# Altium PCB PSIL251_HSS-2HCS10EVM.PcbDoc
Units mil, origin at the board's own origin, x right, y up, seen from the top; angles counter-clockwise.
Board outline 1250 x 1801.18 mil, 4 copper layers (Top Layer, Layer 1, Layer 2, Bottom Layer), stack 49.606 mil thick; 8 components, 13 nets, 43 pads, 12 vias.
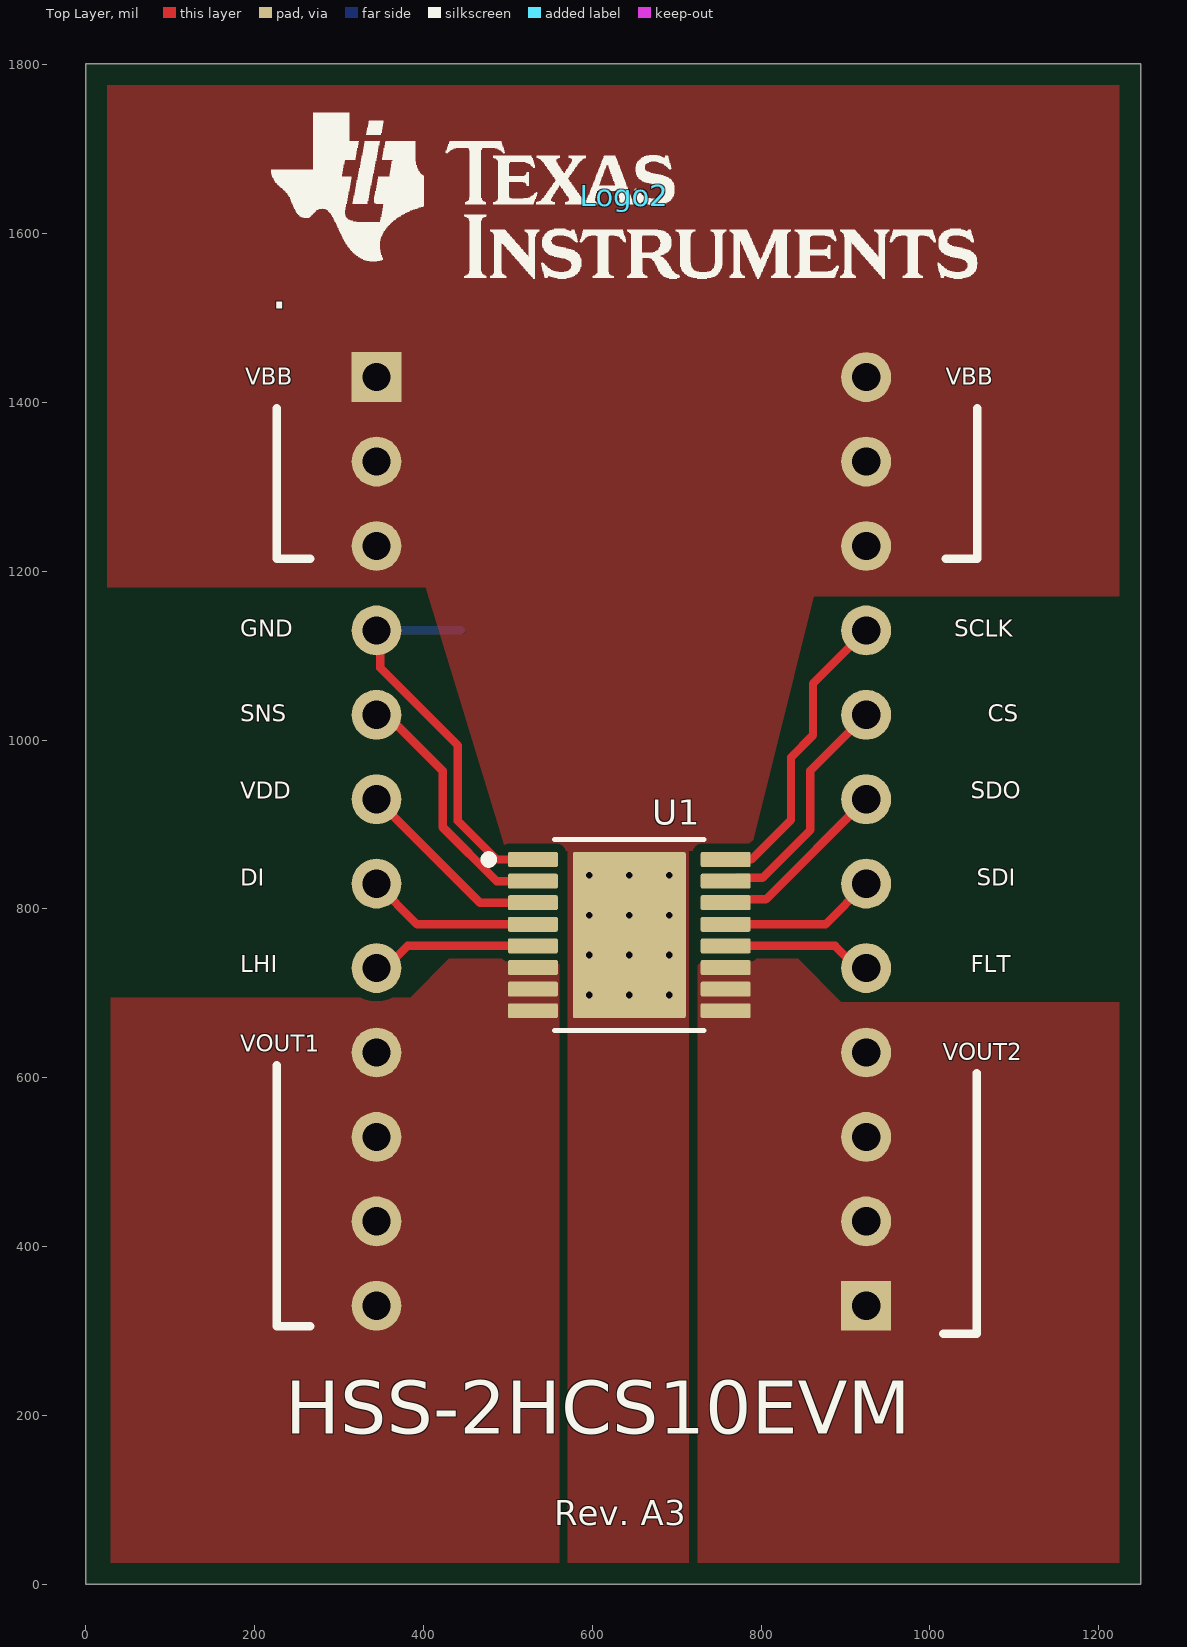
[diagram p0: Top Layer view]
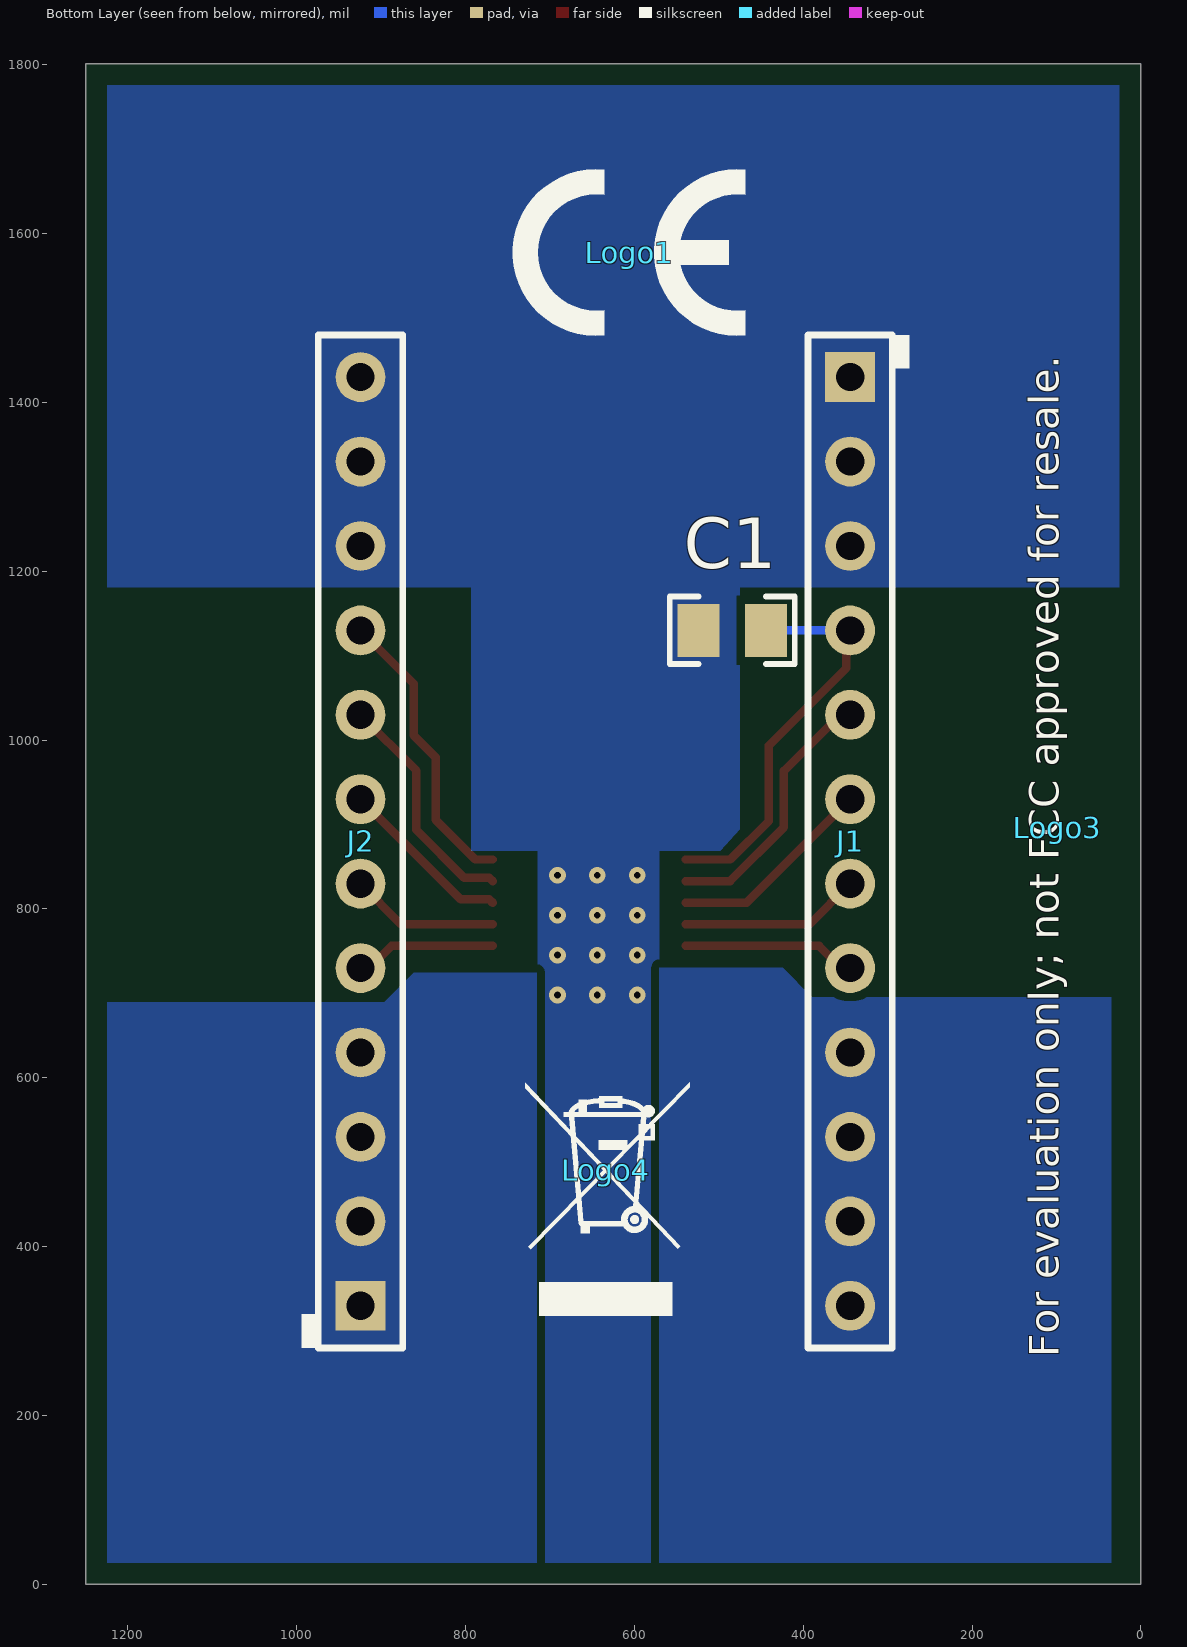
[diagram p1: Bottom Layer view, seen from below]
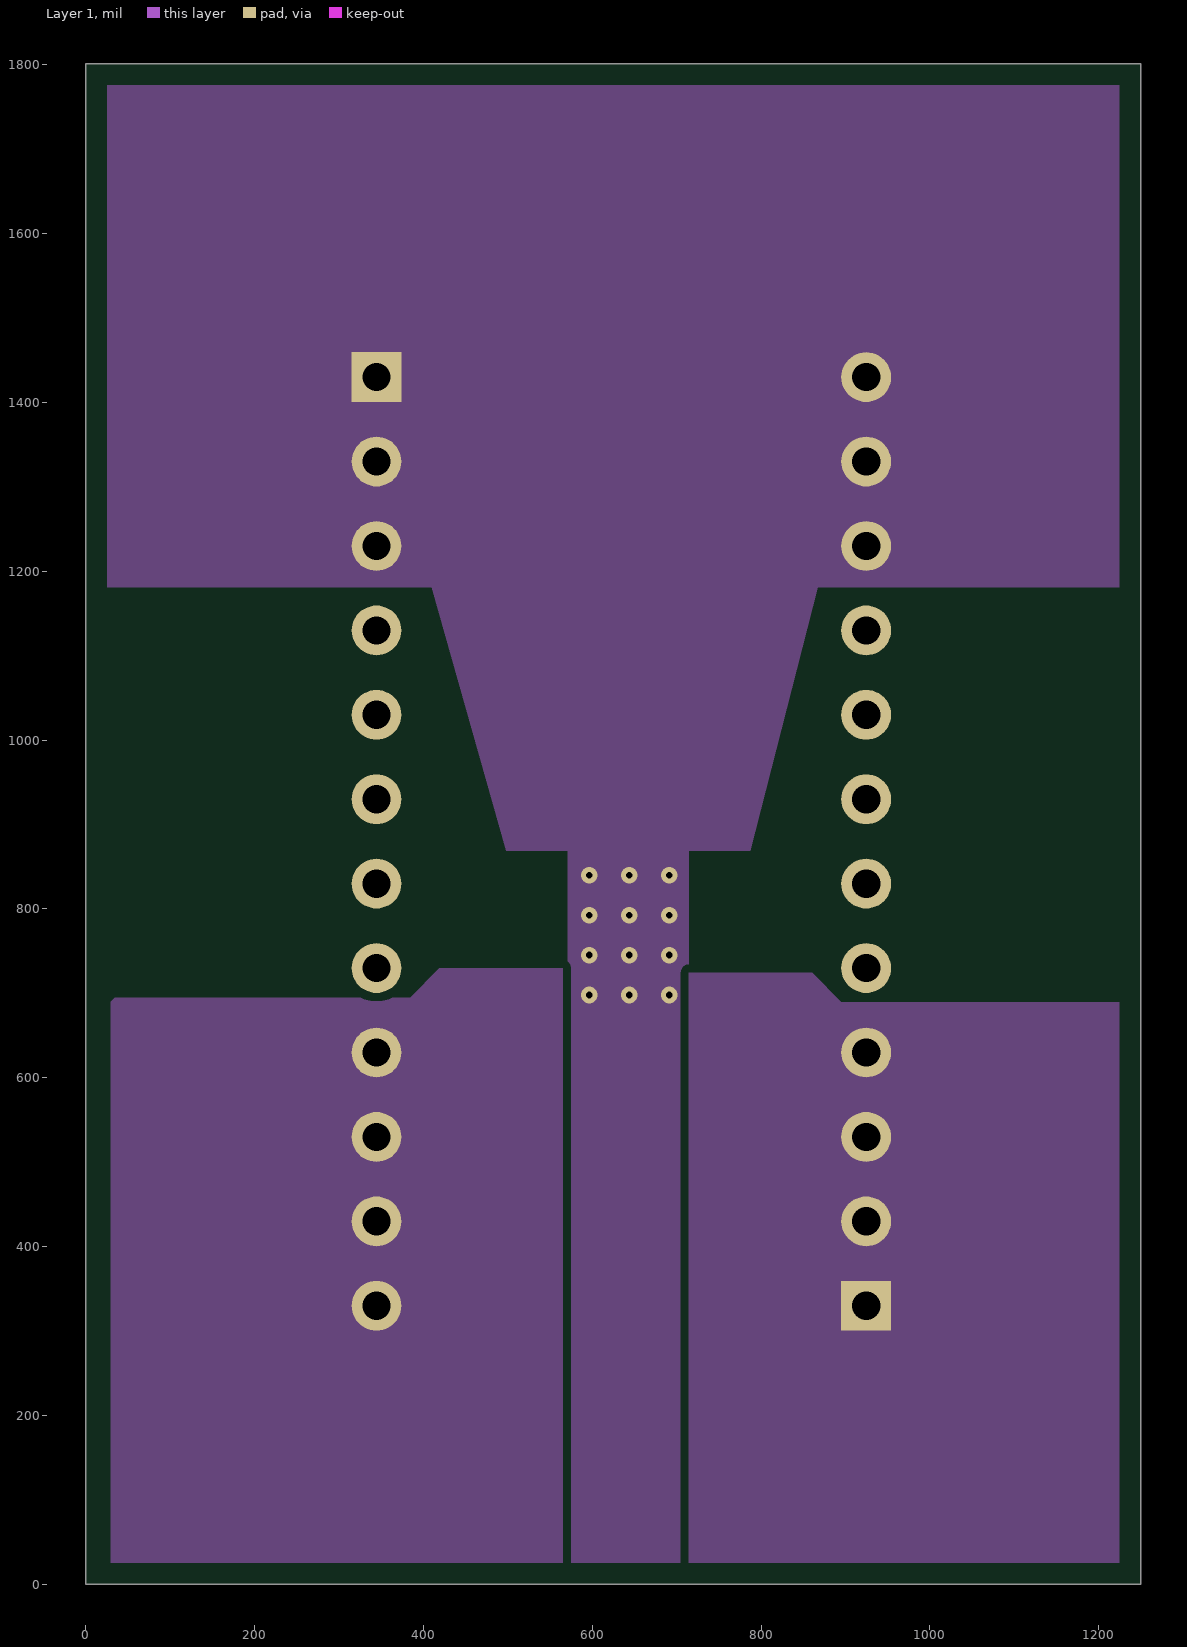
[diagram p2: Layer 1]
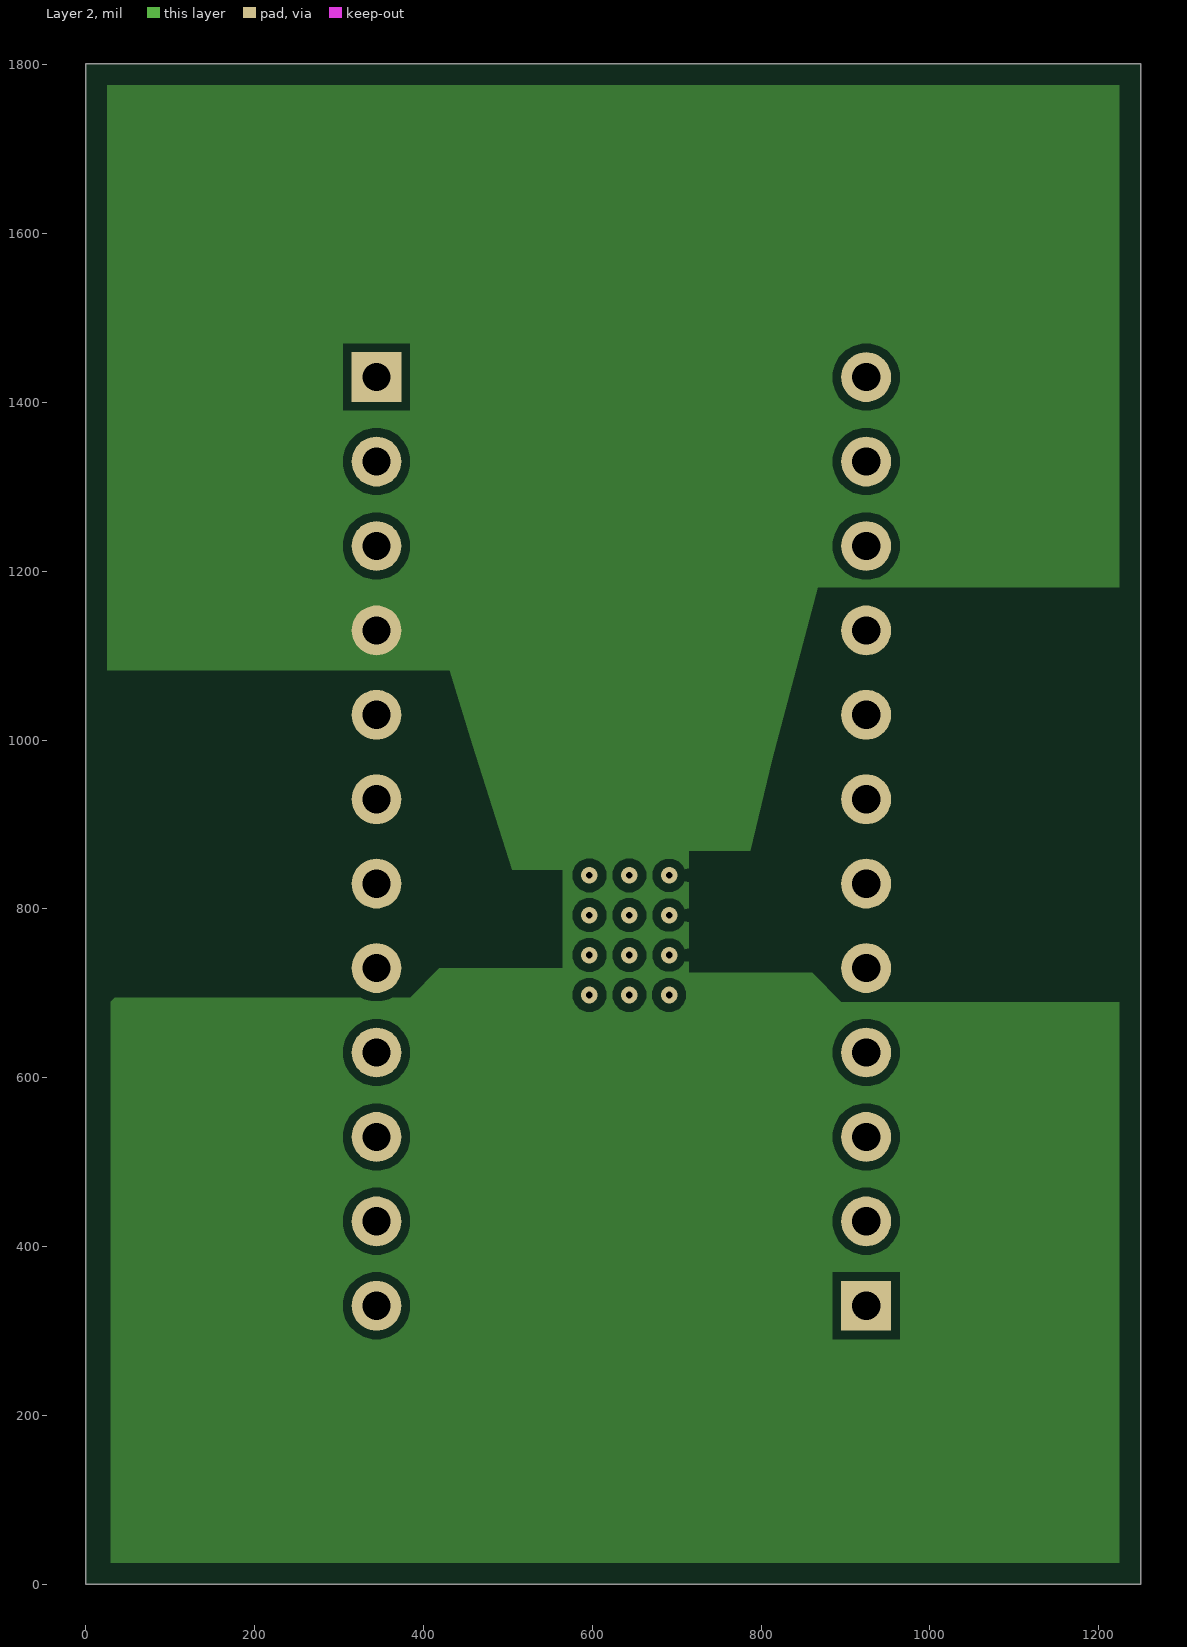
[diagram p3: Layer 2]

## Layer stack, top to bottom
Top Solder: solder mask 0.4, Solder Resist, Dk 3.5
Top Layer: signal copper 1.4
Dielectric 1: prepreg 1.7016, PP-006, Dk 4.1
Layer 1: signal copper 1.7016
Dielectric1: core 40, FR-4 High Tg, Dk 4.8
Layer 2: signal copper 1.7016
Dielectric 2: prepreg 1.7016, PP-006, Dk 4.1
Bottom Layer: signal copper 1.4
Bottom Solder: solder mask 0.4, Solder Resist, Dk 3.5

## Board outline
0,0 1250,0 1250,1801.18 0,1801.18

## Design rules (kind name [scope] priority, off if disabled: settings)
AcuteAngle [All] p1: minimum=4.50000000000000E+0001 checktracksonly=FALSE
AssemblyTestPointUsage [All] p1: valid=2
BoardOutlineClearance BoardOutlineClearance_MountingHoles [OnCopper and InComponentClass('Mounting Holes')] p1: gap=39.37 ignorepadtopadclearanceinfootprint=FALSE
BoardOutlineClearance BoardOutlineClearance_Poly [OnCopper and IsPoly] p2: gap=25 ignorepadtopadclearanceinfootprint=FALSE
BoardOutlineClearance [OnCopper and Not InComponentClass('Logo') and not InComponentClass('FiducialMark') and not InRegion(1000,500,4000,800) and not InPoly] p3: gap=40 ignorepadtopadclearanceinfootprint=FALSE
Clearance Clearance_Keepouts [((IsTrack Or IsArc) And Not InPoly) And IsFree and IsKeepOut vs ((IsTrack Or IsArc) And Not InPoly) And IsFree and IsKeepOut] p1: gap=0 ignorepadtopadclearanceinfootprint=FALSE
Clearance Clearance_Poly [InPolygon] p2: gap=10 ignorepadtopadclearanceinfootprint=TRUE
Clearance Clearance_FiducialMark [IsKeepOut and InComponentClass('FiducialMark') vs IsPad and InComponentClass('FiducialMark')] p3: gap=0 ignorepadtopadclearanceinfootprint=FALSE
Clearance [All] p4: gap=7.87 ignorepadtopadclearanceinfootprint=TRUE
ComponentClearance ComponentClearance_MountingHoles_FiducialMarks [InComponentClass('Mounting Holes') vs InComponentClass('FiducialMark')] p1: gap=50 collisioncheckmode=3 verticalgap=10 showdistances=FALSE
ComponentClearance ComponentClearance_Shunt [InComponentClass('Header') vs InComponentClass('Shunt')] p2: gap=0 collisioncheckmode=3 verticalgap=0 showdistances=FALSE
ComponentClearance ComponentClearance_Logo [InComponentClass('Logo')] p3: gap=30 collisioncheckmode=3 verticalgap=10 showdistances=FALSE
ComponentClearance ComponentClearance_ScrewToNut [(HasFootprint('NY PMS 440 0025 PH')) vs (HasFootprint('Keystone_1902C'))] p4: gap=5 collisioncheckmode=3 verticalgap=10 showdistances=FALSE
ComponentClearance ComponentClearance_MountingHoles [InComponentClass('Mounting Holes')] p5: gap=100 collisioncheckmode=3 verticalgap=100000 showdistances=FALSE
ComponentClearance ComponentClearance_SmallPassives [HasFootprint('0201*') or HasFootprint('0402*') or HasFootprint('0508') or HasFootprint('0603*') or HasFootprint('0612') or HasFootprint('0805*') or HasFootprint('0815*') or HasFootprint('0830*') or HasFootprint('1206*') or HasFootprint('1210*') or HasFootprint('1808*') or HasFootprint('1812*') or HasFootprint('1825*') or HasFootprint('2010*') or HasFootprint('2220*') or HasFootprint('2225*') or HasFootprint('2512*') or HasFootprint('2728*') or HasFootprint('3518*') vs HasFootprint('0201*') or HasFootprint('0402*') or HasFootprint('0508') or HasFootprint('0603*') or HasFootprint('0612') or HasFootprint('0805*') or HasFootprint('0815*') or HasFootprint('0830*') or HasFootprint('1206*') or HasFootprint('1210*') or HasFootprint('1808*') or HasFootprint('1812*') or HasFootprint('1825*') or HasFootprint('2010*') or HasFootprint('2220*') or HasFootprint('2225*') or HasFootprint('2512*') or HasFootprint('2728*') or HasFootprint('3518*')] p6: gap=14.96 collisioncheckmode=3 verticalgap=10 showdistances=FALSE
ComponentClearance ComponentClearance_THtoSMT [IsThruComponent vs IsSMTComponent] p7: gap=30 collisioncheckmode=3 verticalgap=30 showdistances=FALSE
ComponentClearance ComponentClearance_THtoTH [IsThruComponent vs IsThruComponent] p8: gap=20 collisioncheckmode=3 verticalgap=30 showdistances=FALSE
ComponentClearance [All] p9: gap=20 collisioncheckmode=3 verticalgap=10 showdistances=FALSE
DiffPairsRouting [All] p1: maxlimit=100 minlimit=10 mostfreqgap=10 toplayer_minwidth=15 toplayer_maxwidth=15 toplayer_prefwidth=15 midlayer1_minwidth=15 midlayer1_maxwidth=15 midlayer1_prefwidth=15 midlayer2_minwidth=15 midlayer2_maxwidth=15 midlayer2_prefwidth=15 bottomlayer_minwidth=15 bottomlayer_maxwidth=15 bottomlayer_prefwidth=15 maxuncoupledlength=1000
FabricationTestPointUsage TestPointUsage [All] p1: valid=2 allowmultiple=FALSE
FabricationTestpoint Testpoint [All] p1: side=3 testpointundercomponent=TRUE minsize=40 maxsize=100 preferedsize=60 minholesize=0 maxholesize=40 preferedholesize=32 testpointgrid=1 allowsidetop=TRUE allowsidebottom=TRUE usegrid=TRUE gridtolerance=0.01
FanoutControl Fanout_LCC [IsLCC] p1: bgadir=Out bgaviamode=Centered fanoutstyle=Auto fanoutdirection=Alternating viagrid=1 // Fanout_LCC (Default Rule)
FanoutControl Fanout_BGA [IsBGA] p2: bgadir=Out bgaviamode=Centered fanoutstyle=Auto fanoutdirection=Alternating viagrid=1 // Fanout_BGA (Default Rule)
FanoutControl Fanout_Default [All] p4: bgadir=Out bgaviamode=Centered fanoutstyle=Auto fanoutdirection=Alternating viagrid=1 // Fanout_Default (Default Rule)
FanoutControl Fanout_Small [(CompPinCount < 5)] p5: bgadir=Out bgaviamode=Centered fanoutstyle=Auto fanoutdirection=OutThenIn viagrid=1 // Fanout_Small (Default Rule)
HoleSize [All] p1: absolutevalues=TRUE maxlimit=251 minlimit=7.87 maxpercent=80.000 minpercent=20.000
MinimumAnnularRing MinimumAnnularRing_ThermalPadVias [IsVia and InAnyComponent] p1: minimumring=5.91
MinimumAnnularRing [All] p2: minimumring=7.87
MinimumSolderMaskSliver MinimumSolderMaskSliver_Logo [InComponentClass('Logo') vs InComponentClass('Logo')] p1: minsoldermaskwidth=0.7
MinimumSolderMaskSliver [All] p2: minsoldermaskwidth=3.94
PlaneConnect [All] p1: planeconnectstyle=Relief reliefexpansion=10 reliefentries=4 reliefconductorwidth=10 reliefairgap=10
PolygonConnect PolygonConnect_8 [All vs IsNamedPolygon('Top Layer-VBB_1') Or IsNamedPolygon('TOP_LAYER_VOUT1_P008') Or IsNamedPolygon('TOP_LAYER_VOUT2_P006') Or IsNamedPolygon('Layer 1-VBB_1') Or IsNamedPolygon('LAYER_1_VOUT1_P007') Or IsNamedPolygon('LAYER_1_VOUT2_P009') Or IsNamedPolygon('LAYER_2_GND_P017') Or IsNamedPolygon('Bottom Layer-VBB_1') Or IsNamedPolygon('BOTTOM_LAYER_VOUT1_P011') Or IsNamedPolygon('BOTTOM_LAYER_VOUT2_P010')] p1: connectstyle=Direct reliefconductorwidth=10 reliefentries=4 polygonreliefangle="90 Angle" airgapwidth=10
PolygonConnect PolygonConnect_7 [All vs IsNamedPolygon('LAYER_1_VOUT2_P009')] p2: thpad.connectstyle=Direct thpad.reliefconductorwidth=10 thpad.reliefentries=4 thpad.polygonreliefangle="90 Angle" thpad.airgapwidth=10 smdpad.connectstyle=Direct smdpad.reliefconductorwidth=10 smdpad.reliefentries=4 smdpad.polygonreliefangle="90 Angle" smdpad.airgapwidth=10 via.connectstyle=Relief via.reliefconductorwidth=10 via.reliefentries=4 via.polygonreliefangle="90 Angle" via.airgapwidth=10
PolygonConnect PolygonConnect_6 [All vs IsNamedPolygon('LAYER_2_GND_P014')] p3: thpad.connectstyle=Direct thpad.reliefconductorwidth=10 thpad.reliefentries=4 thpad.polygonreliefangle="90 Angle" thpad.airgapwidth=10 smdpad.connectstyle=Direct smdpad.reliefconductorwidth=10 smdpad.reliefentries=4 smdpad.polygonreliefangle="90 Angle" smdpad.airgapwidth=10 via.connectstyle=Relief via.reliefconductorwidth=10 via.reliefentries=4 via.polygonreliefangle="90 Angle" via.airgapwidth=10
PolygonConnect PolygonConnect_5 [All vs IsNamedPolygon('BOTTOM_LAYER_VOUT2_P010')] p4: thpad.connectstyle=Direct thpad.reliefconductorwidth=10 thpad.reliefentries=4 thpad.polygonreliefangle="90 Angle" thpad.airgapwidth=10 smdpad.connectstyle=Direct smdpad.reliefconductorwidth=10 smdpad.reliefentries=4 smdpad.polygonreliefangle="90 Angle" smdpad.airgapwidth=10 via.connectstyle=Relief via.reliefconductorwidth=10 via.reliefentries=4 via.polygonreliefangle="90 Angle" via.airgapwidth=10
PolygonConnect PolygonConnect_4 [All vs IsNamedPolygon('BOTTOM_LAYER_VOUT1_P011')] p5: thpad.connectstyle=Direct thpad.reliefconductorwidth=10 thpad.reliefentries=4 thpad.polygonreliefangle="90 Angle" thpad.airgapwidth=10 smdpad.connectstyle=Direct smdpad.reliefconductorwidth=10 smdpad.reliefentries=4 smdpad.polygonreliefangle="90 Angle" smdpad.airgapwidth=10 via.connectstyle=Relief via.reliefconductorwidth=10 via.reliefentries=4 via.polygonreliefangle="90 Angle" via.airgapwidth=10
PolygonConnect PolygonConnect_3 [All vs IsNamedPolygon('TOP_LAYER_VOUT2_P006')] p6: thpad.connectstyle=Direct thpad.reliefconductorwidth=10 thpad.reliefentries=4 thpad.polygonreliefangle="90 Angle" thpad.airgapwidth=10 smdpad.connectstyle=Direct smdpad.reliefconductorwidth=10 smdpad.reliefentries=4 smdpad.polygonreliefangle="90 Angle" smdpad.airgapwidth=10 via.connectstyle=Relief via.reliefconductorwidth=10 via.reliefentries=4 via.polygonreliefangle="90 Angle" via.airgapwidth=10
PolygonConnect PolygonConnect_2 [All vs IsNamedPolygon('TOP_LAYER_VOUT1_P008')] p7: thpad.connectstyle=Direct thpad.reliefconductorwidth=10 thpad.reliefentries=4 thpad.polygonreliefangle="90 Angle" thpad.airgapwidth=10 smdpad.connectstyle=Direct smdpad.reliefconductorwidth=10 smdpad.reliefentries=4 smdpad.polygonreliefangle="90 Angle" smdpad.airgapwidth=10 via.connectstyle=Relief via.reliefconductorwidth=10 via.reliefentries=4 via.polygonreliefangle="90 Angle" via.airgapwidth=10
PolygonConnect PolygonConnect_1 [All vs IsNamedPolygon('Top Layer-VBB_1') Or IsNamedPolygon('TOP_LAYER_VOUT1_1_P008') Or IsNamedPolygon('TOP_LAYER_VOUT2_1_P006') Or IsNamedPolygon('Layer 1-VBB_1') Or IsNamedPolygon('LAYER_1_VOUT1_P007') Or IsNamedPolygon('LAYER_1_VOUT2_1_P009') Or IsNamedPolygon('LAYER_2_GND_1_P014') Or IsNamedPolygon('Bottom Layer-VBB_1') Or IsNamedPolygon('BOTTOM_LAYER_VOUT1_1_P011') Or IsNamedPolygon('BOTTOM_LAYER_VOUT2_1_P010')] p8: connectstyle=Direct reliefconductorwidth=10 reliefentries=4 polygonreliefangle="90 Angle" airgapwidth=10
PolygonConnect [All] p9: connectstyle=Relief reliefconductorwidth=10 reliefentries=4 polygonreliefangle="90 Angle" airgapwidth=10
RoutingLayers [All] p1: top layer_v5=TRUE mid layer 1_v5=FALSE mid layer 2_v5=FALSE bottom layer_v5=TRUE
RoutingVias ThermalPadVias [IsVia and InAnyComponent] p1: holewidth=7.87 width=19.68 viastyle="Through Hole" minholewidth=7.87 minwidth=19.68 maxholewidth=12.99 maxwidth=23.62
RoutingVias [All] p2: holewidth=16 width=34 viastyle="Through Hole" minholewidth=7.87 minwidth=24 maxholewidth=40 maxwidth=65
SilkToBoardRegionClearance [Not ((IsComment or IsDesignator) And (Hide <> 'False')) and not InRegion(1000,500,4000,800)] p1:
SilkToSilkClearance SilkToSilkClearance_Pb-FreeLogo [(HasFootprint('Pb-Free_Overlay_Medium') OR HasFootprint('Pb-Free_Overlay_Small')) vs (HasFootprint('Pb-Free_Overlay_Medium') OR HasFootprint('Pb-Free_Overlay_Small'))] p1: silktosilkclearance=0
SilkToSilkClearance [All] p2: silktosilkclearance=3.94
SilkToSolderMaskClearance SilkToComponentPadClearance [(IsPad or IsFill or IsRegion) and InAnycomponent] p1: minsilkscreentomaskgap=5 clearancetoexposedcopper=TRUE
SilkToSolderMaskClearance "Silk to Solder Mask Opening" [All] p2: minsilkscreentomaskgap=3.94 clearancetoexposedcopper=FALSE
SolderMaskExpansion [All] p1: expansion=1.97 istentingtop=FALSE
UnRoutedNet [All] p1: checkbadconnections=TRUE
Width [All] p1: maxlimit=100 minlimit=6 preferedwidth=10 checkconnectedcopper=TRUE
13 further rules are at their usual default settings.

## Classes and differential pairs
component class Header: J1 J2
component class PSIL251_HSS-2HCS10EVM: C1 J1 J2 U1

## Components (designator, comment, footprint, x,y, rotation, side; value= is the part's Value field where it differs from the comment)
C1 "CGA4C2NP01H472J060AA" 0805_HV 484.13,1129.92 r180 bottom value=4700pF
J1 "800-10-012-10-001000" Mill-Max_800-10-012-10-001000 344.49,879.92 r270 bottom
J2 "800-10-012-10-001000" Mill-Max_800-10-012-10-001000 924.49,879.92 r90 bottom
Logo1 "CE Mark" CE_Mark_5mm 606.34,1577.52 r180 bottom
Logo2 "Texas Instruments" TI_Stacked_Overlay_Small 637.96,1644.76 r0 top
Logo3 "FCC disclaimer" FCC_disclaimer 99.47,895.88 r90 bottom
Logo4 "WEEE logo" WEEE_Minimum 633.84,490.39 r180 bottom
U1 "TPS2HC10SF-Q1" PWP0016M-MFG 643.87,768.97 r0 top

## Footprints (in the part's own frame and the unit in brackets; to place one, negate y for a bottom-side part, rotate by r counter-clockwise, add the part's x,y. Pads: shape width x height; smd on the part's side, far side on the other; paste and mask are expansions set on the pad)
0805_HV [mil] "0805 with 30mil clearance between pads"
  rect 50x63 smd: 1(-40,0) 2(40,0)
  silkscreen extent -74,-40 74,40, body extent -43,-29 43,29, height 57
CE_Mark_5mm [mil] "Minimum text height for CE Mark"
  silkscreen extent -138,-98 138,98
FCC_disclaimer [mil]
Mill-Max_800-10-012-10-001000 [mm] "Mill-Max"
  rect 1.5x1.5 hole 0.85: 1(-13.97,0)
  round 1.5 hole 0.85: 2(-11.43,0) 3(-8.89,0) 4(-6.35,0) 5(-3.81,0) 6(-1.27,0) 7(1.27,0) 8(3.81,0) 9(6.35,0) 10(8.89,0) 11(11.43,0) 12(13.97,0)
  silkscreen extent -15.24,-1.27 15.24,1.78, body extent -15.24,-1.27 15.24,1.27, height 8.13
PWP0016M-MFG [mm]
  rrect22% 1.5x0.45 smd paste+0 mask+0: 1(-2.9,2.275) 2(-2.9,1.625) 3(-2.9,0.975) 4(-2.9,0.325) 5(-2.9,-0.325) 6(-2.9,-0.975) 7(-2.9,-1.625) 8(-2.9,-2.275) 9(2.9,-2.275) 10(2.9,-1.625) 11(2.9,-0.975) 12(2.9,-0.325) 13(2.9,0.325) 14(2.9,0.975) 15(2.9,1.625) 16(2.9,2.275)
  rrect3% 3.4x5 smd paste-1000 mask-1000: 17(0,0)
  silkscreen extent -4.35,-2.88 2.25,2.88, body extent -3.75,-2.8 3.75,2.8, height 0.25
TI_Stacked_Overlay_Small [mil]
  silkscreen extent -418,-98 418,98
WEEE_Minimum [mil] "WEEElie bin"
  silkscreen extent -95,-172 99,104

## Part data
C1: library part CMP-0080064-1, "CAP, CERM, 4700 pF, 50 V,+/- 5%, C0G/NP0, AEC-Q200 Grade 0, 0805", Cap_Case=0805, Manufacturer=TDK, Supplier Part Number 1=445-12633-1-ND, TempCo=C0G/NP0, Tolerance_%=5%, Value2=50V, ValueDisplayed=4700pF
J1 J2: library part CMP-0055083-1, "Header, 100mil, 12x1, TH", Manufacturer=Mill-Max, Supplier Part Number 1=ED7212-ND
Logo1: library part CMP-0074844-1
Logo2: library part CMP-0074838-1, "Texas Instrument Corporate Signature"
Logo3: library part CMP-0074847-1, "FCC_disclaimer"
Logo4: library part CMP-0074769-1
U1: library part CMP-0098232-1, Manufacturer="Texas Instruments", Operating Temperature Range=to

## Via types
v1: diameter 19.68, hole 7.87, Top Layer to Bottom Layer, tented both sides, 12 vias

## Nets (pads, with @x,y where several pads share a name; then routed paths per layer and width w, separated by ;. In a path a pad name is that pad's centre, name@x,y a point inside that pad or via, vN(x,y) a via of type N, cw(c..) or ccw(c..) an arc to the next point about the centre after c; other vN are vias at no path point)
CS: J2.8 U1.15 | length 279.3
  Top Layer w10: U1.15@767.88,832.94 771.74,836.8 801.6,836.8 858.35,893.55 858.35,963.79 J2.8
DI: J1.7 U1.4 | length 215
  Top Layer w10: J1.7 392.65,781.76 U1.4@539.54,781.76
FLT: J2.5 U1.12 | length 171.2
  Top Layer w10: U1.12@767.88,756.17 887.77,756.17 914.02,729.92 J2.5 J2.5@921.83,732.58
GND: C1.2 J1.4 U1.1 | length 482.9
  Top Layer w10: J1.4 348.98,1125.43 348.98,1085.39 440.83,993.55 440.83,904.16 486.45,858.53 U1.1@539.54,858.53
  Bottom Layer w10: J1.4 C1.2
LHI: J1.8 U1.5 | length 209.7
  Top Layer w10: J1.8@347.15,732.58 J1.8 354.96,729.92 381.21,756.17 U1.5@539.54,756.17
SCLK: J2.9 U1.16 | length 348.4
  Top Layer w10: U1.16@767.88,858.53 788.55,858.53 835.41,905.4 835.41,979.56 861.5,1005.65 861.5,1066.94 J2.9
SDI: J2.6 U1.13 | length 176.6
  Top Layer w10: U1.13@767.88,781.76 876.33,781.76 J2.6
SDO: J2.7 U1.14 | length 207.4
  Top Layer w10: U1.14@767.88,807.35 771.74,811.21 805.78,811.21 J2.7
SNS: J1.5 U1.2 | length 321.3
  Top Layer w10: J1.5@344.49,1024.41 J1.5 356.62,1029.92 422.95,963.59 422.95,896.76 486.77,832.94 U1.2@539.54,832.94
VBB: C1.1 J1.1 J1.2 J1.3 J2.10 J2.11 J2.12 U1.17
  other v1: 596.62,698.1 643.87,698.1 691.11,698.1 596.62,745.35 643.87,745.35 691.11,745.35 596.62,792.59 643.87,792.59 691.11,792.59 596.62,839.83 643.87,839.83 691.11,839.83
VDD: J1.6 U1.3 | length 245.8
  Top Layer w10: J1.6 467.06,807.35 U1.3@539.54,807.35
VOUT1: J1.9 J1.10 J1.11 J1.12 U1.6 U1.7 U1.8
VOUT2: J2.1 J2.2 J2.3 J2.4 U1.9 U1.10 U1.11

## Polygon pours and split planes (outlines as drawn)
VBB on Top Layer "Top Layer-VBB_1" (solid, pour order 4): 0,1181.1 402.7,1181.1 498.08,869.18 570.87,869.18 570.87,0 714.62,0 714.62,869.18 787.29,869.18 862.33,1170.56 1250,1170.56 1250,1801.18 639.76,1801.18 0,1801.18
VOUT1 on Top Layer "TOP_LAYER_VOUT1_P008" (solid, pour order 8): 569.93,745.35 564.91,15.12 29.53,15.12 29.53,694.93 384.33,694.93 434.74,745.35
VOUT2 on Top Layer "TOP_LAYER_VOUT2_P006" (solid, pour order 6): 714.62,743.38 714.62,9.84 1250,9.84 1250,689.65 895.2,689.65 841.48,743.38
VBB on Layer 1 "Layer 1-VBB_1" (solid, pour order 13): 0,1181.1 410.13,1181.1 498.08,869.18 570.87,869.18 570.87,0 714.62,0 714.62,869.18 787.4,869.18 866.97,1181.1 1250,1181.1 1250,1801.18 639.76,1801.18 0,1801.18
VOUT2 on Layer 1 "LAYER_1_VOUT2_P009" (solid, pour order 9): 714.62,724.41 714.62,9.84 1250,9.84 1250,689.65 895.2,689.65 860.45,724.41
VOUT1 on Layer 1 "LAYER_1_VOUT1_P007" (solid, pour order 7): 564.91,729.68 564.91,15.12 29.53,15.12 29.53,690.06 34.39,694.93 384.33,694.93 419.08,729.68
VBB on Bottom Layer "Bottom Layer-VBB_1" (solid, pour order 15): 0,1181.1 475.48,1181.1 475.48,1068.73 475.48,894.53 498.44,869.18 570.87,869.18 570.87,0 714.62,0 714.62,869.18 793.26,869.18 793.26,1181.1 934,1181.1 1250,1181.1 1250,1801.18 639.76,1801.18 0,1801.18
VOUT1 on Bottom Layer "BOTTOM_LAYER_VOUT1_P011" (solid, pour order 11): 570.33,730.24 570.33,15.67 34.95,15.67 34.95,695.48 389.75,695.48 424.5,730.24
VOUT2 on Bottom Layer "BOTTOM_LAYER_VOUT2_P010" (solid, pour order 10): 715.68,724.41 715.68,9.84 1251.06,9.84 1251.06,689.65 896.26,689.65 861.5,724.41
GND on Layer 2 "LAYER_2_GND_P017" (solid, remove dead copper, pour order 17): 0,1801.18 1250,1801.18 1250,1181.1 866.97,1181.1 813.25,978.03 787.4,869.18 714.62,869.18 714.62,724.41 860.45,724.41 895.2,689.65 1224.51,689.65 1224.51,25.49 29.53,25.49 29.53,690.06 34.39,694.93 384.33,694.93 419.08,729.68 564.91,729.68 564.91,846.46 505.28,846.46 458.54,994.09 430.98,1082.68 0,1082.68

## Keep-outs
Keep-Out Layer:
  text ".Layer_Name" at 577,-858.49 h60

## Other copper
Top Layer:
  text ".Layer_Name" at 577,-858.49 h60
Bottom Layer:
  text ".Layer_Name" at 577,-858.49 h60

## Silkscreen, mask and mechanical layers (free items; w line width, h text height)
Top Overlay:
  lines w10: 226.38,614.66 226.38,305.65 265.75,305.65 ; 226.38,1393.09 226.38,1214.66 265.75,1214.66 ; 1015.9,296.64 1055.27,296.64 1055.27,605.65 ; 1018.95,1214.66 1056.16,1214.66 1056.16,1393.09
  text "." at 218.45,1510.93 h50
  text "VBB" at 189.17,1420.66 h20
  text "VBB" at 1018.95,1420.66 h20
  text "GND" at 183.17,1122.42 h20
  text "SCLK" at 1028.61,1122.42 h20
  text "SNS" at 183.17,1021.78 h20
  text "CS" at 1068.6,1021.78 h20
  text "VDD" at 183.17,930.72 h20
  text "SDO" at 1048.6,930.72 h20
  text "DI" at 183.17,827.37 h20
  text "SDI" at 1055.27,827.37 h20
  text "LHI" at 183.17,725.01 h20
  text "FLT" at 1048.6,725.01 h20
  text "VOUT1" at 183.17,630.72 h20
  text "VOUT2" at 1015.28,620.66 h20
  text "HSS-2HCS10EVM" at 236.22,157.48 h108.27
  text "Rev. A3" at 555.29,60 h50
  text ".Layer_Name" at 577,-858.49 h60
Bottom Overlay:
  text ".Layer_Name" at 577,-858.49 h60
Top Paste:
  text ".Layer_Name" at 577,-858.49 h60
Bottom Paste:
  text ".Layer_Name" at 577,-858.49 h60
Top Solder:
  text ".Layer_Name" at 577,-858.49 h60
  text ".Layer_Name" at 577,-858.49 h60
Bottom Solder:
  text ".Layer_Name" at 577,-858.49 h60
Drill Guide:
  text ".Layer_Name" at 577,-858.49 h60
M1 Board Outline:
  lines w10: 0,1801.18 0,0 1250.71,0 1250,1801.18 4.92,1801.18
  text ".Layer_Name" at 577,-858.49 h60
M2 Board Dimensions:
  rectangle: 0,-275 125,-150
  rectangle: 125,-400 500,-275
  lines w7: 0,-275 1000,-275 ; 125,-400 125,-150 ; 250,-400 250,-150 ; 500,-400 500,-150 ; 750,-400 750,-150 ; 0,-400 1000,-400 1000,-150 0,-150 0,-400
  text ".Layer_Name" at 577,-858.49 h60
M3 3D STEP Top:
  text ".Layer_Name" at 577,-858.49 h60
M4 3D STEP Bottom:
  text ".Layer_Name" at 577,-858.49 h60
M5 Assembly Top:
  lines w10: -292,-930.17 6308,-930.17 ; -292,-726.83 6310,-726.83 ; -292,-523.5 -292,-1133.5 3713,-1133.5 6310,-1133.5 6310,-523.5 -291.5,-523.5 -291.5,-1133.5 1284,-1133.5 ; 2173,-1133.5 2173,-523.5 ; 3440,-726.83 3440,-523.5 ; 4280,-726.83 4280,-523.5 ; 4902,-1140 4902,-937.17
  text "COMPONENTS MARKED 'DNP' SHOULD NOT BE POPULATED." at 1153.5,-318.5 h60
  text "ASSEMBLY VARIANT:" at 1153,-434 h60
  text ".VariantName" at 2189,-434 h60
  text "PCB VIEWED FROM TOP SIDE" at -228.5,-655.67 h60
  text "BOARD #:" at 2248,-655.67 h60
  text ".PRJ_Number" at 2793.5,-655.67 h60
  text "REV:" at 3638,-655.67 h60
  text ".PCB_Rev" at 3929.5,-655.67 h60
  text "SVN REV:" at 4476,-655.67 h60
  text ".VersionControl_RevNumber" at 4982,-655.67 h60
  text "TID #:" at 2248,-859 h60
  text ".TID" at 2793.5,-859 h60
  text "PLOT NAME =" at -228.5,-1064.34 h60
  text ".plot_File_Name" at 577,-1064.34 h60
  text "GENERATED    :" at 2250,-1064.34 h60
  text ".Print_Date" at 3119.5,-1064.34 h60
  text ".Print_Time" at 3848.5,-1064.34 h60
  text "TEXAS INSTRUMENTS" at 5113,-1064.34 h60
M6 Assembly Bottom:
  lines w10: -292.5,-727.33 6309.5,-727.33 ; -290.5,-930.67 6309.5,-930.67 ; 1115.5,-1140.5 1115.5,-937.67 ; 1737.5,-727.33 1737.5,-524 ; 2577.5,-727.33 2577.5,-524 ; 3844.5,-1134 3844.5,-524 ; 4733.5,-1134 6309,-1134 6309,-524 -292.5,-524 -292.5,-1134 2304.5,-1134 6309.5,-1134 6309.5,-524
  text "COMPONENTS MARKED 'DNP' SHOULD NOT BE POPULATED." at 6102,-318 h60
  text ".VariantName" at 5058,-434 h60
  text "ASSEMBLY VARIANT:" at 6097,-434 h60
  text ".VersionControl_RevNumber" at 1035.5,-656.17 h60
  text "SVN REV:" at 1541.5,-656.17 h60
  text ".PCB_Rev" at 2088,-656.17 h60
  text "REV:" at 2379.5,-656.17 h60
  text ".PRJ_Number" at 3224,-656.17 h60
  text "BOARD #:" at 3769.5,-656.17 h60
  text "PCB VIEWED FROM BOTTOM SIDE" at 6246,-656.17 h60
  text ".TID" at 3224,-859.5 h60
  text "TID #:" at 3769.5,-859.5 h60
  text "TEXAS INSTRUMENTS" at 904.5,-1064.84 h60
  text ".Print_Time" at 2169,-1064.84 h60
  text ".Print_Date" at 2898,-1064.84 h60
  text "GENERATED    :" at 3767.5,-1064.84 h60
  text ".plot_File_Name" at 5440.5,-1064.84 h60
  text "PLOT NAME =" at 6246,-1064.84 h60
M9 Title Sheet:
  drawing of 57 lines, arcs and shapes, not listed
  text "1" at 739.84,8036.5 h70
  text "2" at 3235.5,8036.5 h70
  text "3" at 5724.84,8036.5 h70
  text "4" at 8231.51,8036.5 h70
  text "5" at 10730.5,8036.5 h70
  text "6" at 13235.5,8036.5 h70
  text "A" at -416.5,6893.5 h70
  text "A" at 14383.5,6893.5 h70
  text "B" at -416.5,4513.5 h70
  text "B" at 14383.5,4513.5 h70
  text "C" at -416.5,2138.5 h70
  text "C" at 14383.5,2138.5 h70
  text "PROJECT TITLE:" at 11343.5,277.5 h45
  text ".PRJ_Title" at 11393.5,144.17 h70
  text "DESIGNED FOR:" at 11343.5,-23.5 h45
  text ".PRJ_Customer" at 11393.5,-163.5 h70
  text "D" at -416.5,-231.5 h70
  text "D" at 14383.5,-231.5 h70
  text "FILE NAME:" at 11343.5,-323.5 h45
  text ".PCB_File_Name_No_Path" at 11393.5,-443.5 h70
  text "Texas Instruments (TI) and/or its licensors do not warrant the accuracy or completeness of this specification" at 6374,-605.34 h45
  text "ENGINEER:" at 11343.5,-613.5 h45
  text "LAYOUT BY:" at 12848.5,-613.5 h45
  text "or any information contained therein. TI and/or its licensors do not warrant that this design will meet" at 6329.01,-718 h45
  text ".PRJ_Engineer" at 11393.5,-768.49 h70
  text ".PCB_Layout" at 12899,-768.49 h70
  text "the specifications, will be suitable for your application or fit for any particular purpose, or will operate in" at 6329.01,-830.67 h45
  text ".Layer_Name" at 577,-858.49 h60
  text "ALTIUM DESIGNER VERSION:" at 12848.5,-923.5 h45
  text "an implementation. TI and/or its licensors do not warrant that the design is production worthy. You should" at 6329.01,-943.33 h45
  text "completely validate and test your design implementation to confirm the system functionality for your application." at 6374,-1056 h45
  text ".print_Scale" at 11393.5,-1056.83 h70
  text ".Application_BuildNumber" at 12899,-1056.83 h70
  text "1" at 739.84,-1263.5 h70
  text "2" at 3235.5,-1263.5 h70
  text "3" at 5724.84,-1263.5 h70
  text "4" at 8231.51,-1263.5 h70
  text "5" at 10730.5,-1263.5 h70
  text "6" at 13235.5,-1263.5 h70
M10 Fab Notes:
  drawing of 189 lines, arcs and shapes, not listed
  text "DESIGN INFORMATION" at 12382.02,6356.17 h60
  text "MIN. TRACK WIDTH:" at 11737.46,6224.05 h60
  text "8" at 12833.7,6224.05 h60
  text "MIL" at 12988.46,6224.05 h60
  text "7.874" at 12667.32,6102.36 h60
  text "MIN. CLEARANCE:" at 11737.46,6099.92 h60
  text "MIL" at 12988.46,6099.92 h60
  text "MIN. VIA PAD SIZE:" at 11737.46,5975.8 h60
  text "24" at 12803.71,5975.8 h60
  text "MIL" at 12988.46,5975.8 h60
  text "0.05mm (2MIL)" at 12432.46,5845.9 h60
  text "MINIMUM ANNULAR RING" at 11408.23,5837.67 h60
  text "EXTERNAL" at 13140.46,5837.67 h60
  text "PER" at 11608.23,5727.55 h60
  text "IPC-D-275 CLASS 2 LEVEL C" at 11828.23,5727.54 h60
  text "MIL, HOLES" at 13316.46,5627.07 h60
  text "+/-" at 12924,5618.48 h60
  text "+/-" at 13778,5618.48 h60
  text "REGISTRATION TOLERANCES:" at 11408.23,5617.42 h60
  text "METAL" at 12608,5617.42 h60
  text "5" at 13184.2,5617.42 h60
  text "3" at 14017.2,5617.42 h60
  text "MIL" at 14133.46,5617.42 h60
  text "HOLE SIZE TOLERANCE (UNLESS OTHERWISE SPECIFIED):" at 11408.23,5519.1 h60
  text "+/-" at 13778,5516.23 h60
  text "3" at 14017.2,5515.17 h60
  text "MIL" at 14133.46,5515.17 h60
  text "MATERIAL:" at 11333.46,5377.52 h60
  text "FR-4 High Tg" at 12319.9,5249 h60
  text "X" at 12175.46,5241.01 h60
  text "FR-408" at 11754.46,5236.49 h60
  text "OTHER" at 13242.46,5236.49 h60
  text "62 MIL (1.6mm) +/-10%" at 12074.56,5093.46 h60
  text "X" at 11954.46,5091.01 h60
  text "THICKNESS:" at 11408.23,5085.24 h60
  text "OTHER" at 13359.46,5085.24 h60
  text "TOLERANCE:" at 11408.23,4946.92 h60
  text "X" at 12256.46,4946.92 h60
  text "ANSI IPC-6012 TYPE 3 CLASS 2" at 12434.48,4946.92 h60
  text "OTHER +/-" at 12434.46,4802.73 h60
  text "BOW & TWIST:" at 11408.23,4657.54 h60
  text "X" at 12256.46,4657.54 h60
  text "ANSI IPC-6012 TYPE 3 CLASS 2" at 12434.48,4657.54 h60
  text "OTHER +/-" at 12434.46,4510.85 h60
  text "DRILLING:" at 11333.46,4380.23 h60
  text "NC_DRILL FILES" at 13094.46,4275.04 h60
  text "REFERENCE:" at 11408.23,4271.1 h60
  text "X" at 12065.46,4271.01 h60
  text "AS SHOWN" at 12243.46,4271.1 h60
  text "X" at 12966.46,4271.1 h60
  text "OTHER" at 13392.46,4128.85 h60
  text "PTH COPPER THICKNESS:" at 11407.91,4125.32 h60
  text "X" at 12547.14,4125.32 h60
  text "20-30 um" at 12675.14,4125.32 h60
  text "BOARD FINISH:" at 11333.46,3977.73 h60
  text "SILKSCREEN:" at 11488.68,3867.6 h60
  text "X" at 12446.46,3867.6 h60
  text "TOP" at 12563.46,3867.6 h60
  text "X" at 12956.46,3867.6 h60
  text "BOTTOM" at 13074.46,3867.6 h60
  text "SILKSCREEN COLOR:" at 11488.68,3712.41 h60
  text "X" at 12446.46,3712.41 h60
  text "OTHER" at 13074.46,3712.41 h60
  text "WHITE" at 12569.27,3710.32 h60
  text "PURPLE" at 13656.46,3572.03 h60
  text "GREEN" at 12694.46,3568.96 h60
  text "X" at 13162.46,3568.96 h60
  text "OTHER" at 13312.46,3568.96 h60
  text "SOLDER RESIST COLOR:" at 11488.68,3562.1 h60
  text "MATTE" at 12694.46,3414.71 h60
  text "X" at 13162.46,3414.71 h60
  text "SEMI-GLOSS" at 13312,3414.07 h60
  text "IMMERSION GOLD (ENIG)" at 12394.46,3241.94 h60
  text "ENEPIG" at 13732,3234.72 h60
  text "SURFACE FINISH:" at 11333.46,3233.72 h60
  text "X" at 12216.46,3233.72 h60
  text "IMM. TIN/SILVER OR EQUIV" at 11663,3096.4 h60
  text "OTHER" at 13094.46,3092.47 h60
  text "ARRAY/PANEL:" at 11333.46,2937.09 h60
  text "CUT AND TRIM PER M1 BOARD OUTLINE" at 12394.46,2928.87 h60
  text "N.C. ROUTE" at 12394.46,2792.9 h60
  text "X" at 13082.46,2792.9 h60
  text "V. SCORE" at 13260.46,2792.9 h60
  text "CERTIFICATION:" at 11333.46,2663.77 h60
  text "MATERIALS AND WORKMANSHIP FOR ALL PCBS" at 12058.46,2663.77 h60
  text "TO MEET OR EXCEED THE REQUIREMENTS OF:" at 12058.46,2569.71 h60
  text "X" at 11695.97,2441.08 h60
  text "ANSI IPC-A-600F CLASS ->" at 11823.96,2441.08 h60
  text "X" at 13471.97,2441.08 h60
  text "2" at 13581.96,2441.08 h60
  text "1" at 13266.96,2439.58 h60
  text "3" at 13935.96,2439.58 h60
  text "X" at 12507.97,2293.39 h60
  text "RoHS" at 12635.96,2293.39 h60
  text "OTHER" at 13280.36,2293.39 h60
  text "PER ORDER" at 13677.42,2293.39 h60
  text "ALL BOARDS MUST MEET OR EXCEED UL94-V0 REQUIREMENTS." at 11361,2139.57 h60
  text "PCB MUST BEAR THE UL94V-0 UL REGISTERED MATERIAL ID NUMBER" at 11361,2023.5 h60
  text "ADDITIONAL REQUIREMENTS:" at 11333.46,1854.08 h60
  text "MICROSECTION:" at 11408.23,1746.95 h60
  text "YES" at 12313.96,1746.95 h60
  text "REQUIRED" at 13175.46,1602.62 h60
  text "BARE BOARD ELEC. TEST:" at 11408.23,1599.76 h60
  text "NONE" at 12713.96,1599.76 h60
  text "X" at 13057.46,1599.76 h60
  text "PER ORDER" at 13767.46,1599.76 h60
  text "XX MIL VIAS REQUIRE NON-CONDUCTIVE FILL AND PLANARIZE" at 11576.38,1394.82 h59
  text "XX MIL VIAS REQUIRE CONDUCTIVE FILL AND PLANARIZE" at 11584.38,1290.84 h60
  text "OUTER XX MIL TRACES REQUIRE 50 OHM SINGLE-ENDED IMPEDANCE" at 11583.39,1127.46 h58
  text "LAYER 2 & 3 (INNER LAYERS) XX MIL WIDE, XX MIL SPACE / TRACES REQUIRE 100 OHM DIFFERENTIAL IMPEDANCE" at 11575.39,891.74 h60
  text ".Layer_Name" at 577,-858.49 h60
M11 Gerber Information:
  lines w10: -292,-930.17 6308,-930.17 ; -292,-726.83 6310,-726.83 ; -292,-523.5 -292,-1133.5 3713,-1133.5 6310,-1133.5 6310,-523.5 -291.5,-523.5 -291.5,-1133.5 1284,-1133.5 ; 2173,-1133.5 2173,-523.5 ; 3440,-726.83 3440,-523.5 ; 4280,-726.83 4280,-523.5 ; 4902,-1140 4902,-937.17
  text "ALL ARTWORK VIEWED FROM TOP SIDE" at -228.5,-655.67 h60
  text "BOARD #:" at 2248,-655.67 h60
  text ".PRJ_Number" at 2793.5,-655.67 h60
  text "REV:" at 3638,-655.67 h60
  text ".PCB_Rev" at 3929.5,-655.67 h60
  text "SVN REV:" at 4476,-655.67 h60
  text ".VersionControl_RevNumber" at 4982,-655.67 h60
  text "LAYER NAME =" at -228.5,-858.49 h60
  text "TID #:" at 2248,-859 h60
  text ".TID" at 2793.5,-859 h60
  text "PLOT NAME =" at -228.5,-1064.34 h60
  text ".plot_File_Name" at 577,-1064.34 h60
  text "GENERATED    :" at 2250,-1064.34 h60
  text ".Print_Date" at 3119.5,-1064.34 h60
  text ".Print_Time" at 3848.5,-1064.34 h60
  text "TEXAS INSTRUMENTS" at 5113,-1064.34 h60
M12 Stackup:
  drawing of 295 lines, arcs and shapes, not listed
  text "Layer" at 9821.59,7874.94 h60
  text "Name" at 10231.51,7874.94 h60
  text "Material" at 11161.25,7874.94 h60
  text "Thickness" at 12021.02,7874.94 h60
  text "Constant" at 12670.85,7874.94 h60
  text "Board Layer Stack" at 13240.71,7874.94 h60
  text "Top Overlay" at 10231.51,7754.94 h60
  text "Top Solder" at 10231.51,7634.94 h60
  text "Solder Resist" at 11161.25,7634.94 h60
  text "0.40mil" at 12021.02,7634.94 h60
  text "3.5" at 12670.85,7634.94 h60
  text "1" at 9821.59,7514.94 h60
  text "Top Layer" at 10231.51,7514.94 h60
  text "1.40mil" at 12021.02,7514.94 h60
  text "Dielectric 1" at 10231.51,7394.94 h60
  text "PP-006" at 11161.25,7394.94 h60
  text "1.70mil" at 12021.02,7394.94 h60
  text "4.1" at 12670.85,7394.94 h60
  text "2" at 9821.59,7274.94 h60
  text "Layer 1" at 10231.51,7274.94 h60
  text "CF-004" at 11161.25,7274.94 h60
  text "1.70mil" at 12021.02,7274.94 h60
  text "Dielectric1" at 10231.51,7154.94 h60
  text "FR-4 High Tg" at 11161.25,7154.94 h60
  text "40.00mil" at 12021.02,7154.94 h60
  text "4.8" at 12670.85,7154.94 h60
  text "3" at 9821.59,7034.94 h60
  text "Layer 2" at 10231.51,7034.94 h60
  text "CF-004" at 11161.25,7034.94 h60
  text "1.70mil" at 12021.02,7034.94 h60
  text "Dielectric 2" at 10231.51,6914.94 h60
  text "PP-006" at 11161.25,6914.94 h60
  text "1.70mil" at 12021.02,6914.94 h60
  text "4.1" at 12670.85,6914.94 h60
  text "4" at 9821.59,6794.94 h60
  text "Bottom Layer" at 10231.51,6794.94 h60
  text "1.40mil" at 12021.02,6794.94 h60
  text "Bottom Solder" at 10231.51,6674.94 h60
  text "Solder Resist" at 11161.25,6674.94 h60
  text "0.40mil" at 12021.02,6674.94 h60
  text "3.5" at 12670.85,6674.94 h60
  text "Bottom Overlay" at 10231.51,6554.94 h60
  text ".Layer_Name" at 577,-858.49 h60
M13 Component Bodies Top:
  text ".Layer_Name" at 577,-858.49 h60
M14 Component Bodies Bottom:
  text ".Layer_Name" at 577,-858.49 h60
M15 Courtyards Top:
  text ".Layer_Name" at 577,-858.49 h60
M16 Courtyards Bottom:
  text ".Layer_Name" at 577,-858.49 h60
Drill Drawing:
  lines w10: 5335.98,3139.13 5391.1,3139.13 5391.1,3194.25 5335.98,3194.25 5335.98,3139.13 ; 5335.98,3318.28 5391.1,3318.28 5363.54,3263.15 5335.98,3318.28
  lines w12: 5286,3101.92 8512.8,3101.92 ; 5286,3349.97 8512.8,3349.97 ; 5623.36,2977.89 5623.36,3474 ; 5955.06,2977.89 5955.06,3474 ; 6590.91,2977.89 6590.91,3474 ; 6849.71,2977.89 6849.71,3474 ; 7224.46,2977.89 7224.46,3474 ; 7947,2977.89 7947,3474 ; 5286,2977.89 8512.8,2977.89 8512.8,3474 5286,3474 5286,2977.89
  text "Symbol" at 5360.42,3387.18 h72
  text "Quantity" at 5660.57,3387.18 h72
  text "Finished Hole Size" at 5992.26,3387.18 h72
  text "Plated" at 6628.12,3387.18 h72
  text "Hole Type" at 6886.92,3387.18 h72
  text "Drill Layer Pair" at 7261.67,3387.18 h72
  text "Hole Tolerance" at 7984.21,3387.18 h72
  text "12" at 5660.57,3263.15 h60
  text "7.87mil (0.200mm)" at 5992.26,3263.15 h60
  text "PTH" at 6628.12,3263.15 h60
  text "Round" at 6886.92,3263.15 h60
  text "Top Layer - Bottom Layer" at 7261.67,3263.15 h60
  text "24" at 5660.57,3139.13 h60
  text "33.47mil (0.850mm)" at 5992.26,3139.13 h60
  text "PTH" at 6628.12,3139.13 h60
  text "Round" at 6886.92,3139.13 h60
  text "Top Layer - Bottom Layer" at 7261.67,3139.13 h60
  text "36 Total" at 5660.57,3015.1 h60
  text ".Layer_Name" at 577,-858.49 h60
M17 Embedded Cavity:
  text ".Layer_Name" at 577,-858.49 h60
M18 Embedded Assembly:
  text ".Layer_Name" at 577,-858.49 h60
M19 Embedded Keepout:
  text ".Layer_Name" at 577,-858.49 h60

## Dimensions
0,-400 to 1000,-400 on M2 Board Dimensions
0,0 to 0,1801.18 on M2 Board Dimensions
0,0 to 1250,0 on M2 Board Dimensions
